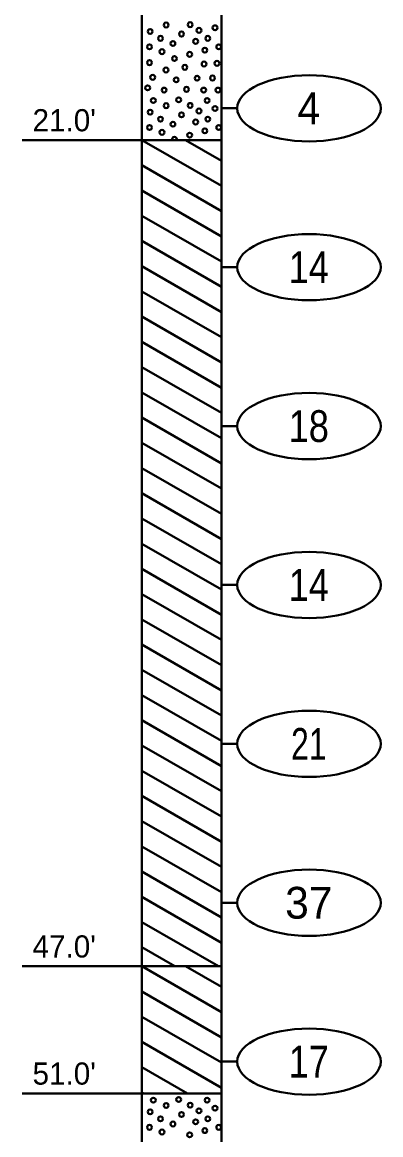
# Model space of a CAD drawing. Extents: x -76 to 974, y -1080 to -735.
# Drawn here: x 11.33 to 22.61, y -820.52 to -785.51 of the extents above; entities that cross this region are included whole.
import ezdxf
from ezdxf.enums import TextEntityAlignment as Align

# ---------------------------------------------------------------- set-up
doc = ezdxf.new("R2010")
doc.units = 0
doc.header["$LTSCALE"] = 0.36
doc.layers.add('27', color=7, linetype='Continuous', lineweight=40)

msp = doc.modelspace()

# ---------------------------------------------------------------- linework, layer by layer
at = {"layer": '27'}
for p, q in [((15.0967, -785.2173), (15.0967, -789.2173)), ((17.5967, -789.2173), (17.5967, -785.2173)), ((18.0967, -788.2173), (17.5967, -788.2173)), ((11.3293, -789.2173), (15.0966, -789.2173)), ((15.0967, -789.2173), (17.5967, -789.2173)), ((15.0967, -789.2173), (17.5967, -790.6607)), ((15.0967, -789.2173), (15.0967, -815.2173)), ((16.4714, -789.2173), (17.5967, -789.8669)), ((16.4714, -789.2173), (17.5967, -789.8669)), ((17.5967, -815.2173), (17.5967, -789.2173)), ((15.0967, -790.011), (17.5967, -791.4544)), ((15.0967, -790.011), (17.5967, -791.4544)), ((15.0967, -790.8048), (17.5967, -792.2482)), ((15.0967, -791.5985), (17.5967, -793.0419)), ((15.0967, -791.5985), (17.5967, -793.0419)), ((15.0967, -792.3923), (17.5967, -793.8357)), ((15.0967, -793.186), (17.5967, -794.6294)), ((15.0967, -793.186), (17.5967, -794.6294)), ((18.0967, -793.2173), (17.5967, -793.2173)), ((15.0967, -793.9798), (17.5967, -795.4232)), ((15.0967, -794.7735), (17.5967, -796.2169)), ((15.0967, -794.7735), (17.5967, -796.2169)), ((15.0967, -795.5673), (17.5967, -797.0107)), ((15.0967, -796.361), (17.5967, -797.8044)), ((15.0967, -796.361), (17.5967, -797.8044)), ((15.0967, -797.1548), (17.5967, -798.5982)), ((15.0967, -797.9485), (17.5967, -799.3919)), ((15.0967, -797.9485), (17.5967, -799.3919)), ((18.0967, -798.2173), (17.5967, -798.2173)), ((15.0967, -798.7423), (17.5967, -800.1857)), ((15.0967, -799.536), (17.5967, -800.9794)), ((15.0967, -799.536), (17.5967, -800.9794)), ((15.0967, -800.3298), (17.5967, -801.7732)), ((15.0967, -801.1235), (17.5967, -802.5669)), ((15.0967, -801.1235), (17.5967, -802.5669)), ((15.0967, -801.9173), (17.5967, -803.3607)), ((15.0967, -802.711), (17.5967, -804.1544)), ((15.0967, -802.711), (17.5967, -804.1544)), ((18.0967, -803.2173), (17.5967, -803.2173)), ((15.0967, -803.5048), (17.5967, -804.9482)), ((15.0967, -804.2985), (17.5967, -805.7419)), ((15.0967, -804.2985), (17.5967, -805.7419)), ((15.0967, -805.0923), (17.5967, -806.5357)), ((15.0967, -805.886), (17.5967, -807.3294)), ((15.0967, -805.886), (17.5967, -807.3294)), ((15.0967, -806.6798), (17.5967, -808.1232)), ((15.0967, -807.4735), (17.5967, -808.9169)), ((15.0967, -807.4735), (17.5967, -808.9169)), ((15.0967, -808.2673), (17.5967, -809.7107)), ((18.0967, -808.2173), (17.5967, -808.2173)), ((15.0967, -809.061), (17.5967, -810.5044)), ((15.0967, -809.061), (17.5967, -810.5044)), ((15.0967, -809.8548), (17.5967, -811.2982)), ((15.0967, -810.6485), (17.5967, -812.0919)), ((15.0967, -810.6485), (17.5967, -812.0919)), ((15.0967, -811.4423), (17.5967, -812.8857)), ((15.0967, -812.236), (17.5967, -813.6794)), ((15.0967, -812.236), (17.5967, -813.6794)), ((15.0967, -813.0298), (17.5967, -814.4732)), ((18.0967, -813.2173), (17.5967, -813.2173)), ((15.0967, -813.8235), (17.5106, -815.2173)), ((15.0967, -813.8235), (17.5106, -815.2173)), ((15.0967, -814.6173), (16.1359, -815.2173)), ((11.3293, -815.2173), (15.0966, -815.2173)), ((15.0967, -815.2173), (17.5967, -815.2173)), ((15.0967, -815.2173), (17.5967, -816.6607)), ((15.0967, -815.2173), (15.0967, -819.2173)), ((16.4714, -815.2173), (17.5967, -815.8669)), ((16.4714, -815.2173), (17.5967, -815.8669)), ((17.5967, -819.2173), (17.5967, -815.2173)), ((15.0967, -816.011), (17.5967, -817.4544)), ((15.0967, -816.011), (17.5967, -817.4544)), ((15.0967, -816.8048), (17.5967, -818.2482)), ((15.0967, -817.5985), (17.5967, -819.0419)), ((15.0967, -817.5985), (17.5967, -819.0419)), ((15.0967, -818.3923), (16.5256, -819.2173)), ((18.0967, -818.2173), (17.5967, -818.2173)), ((15.0967, -819.186), (15.1508, -819.2173)), ((15.0967, -819.186), (15.1508, -819.2173)), ((11.3293, -819.2173), (15.0966, -819.2173)), ((15.0967, -819.2173), (17.5967, -819.2173)), ((15.0967, -819.2173), (15.0967, -838.7173)), ((17.5967, -838.7173), (17.5967, -819.2173))]:
    msp.add_line(p, q, dxfattribs=at)
for points in [[(15.9335, -785.5952), (15.9233, -785.5571), (15.8954, -785.5292), (15.8573, -785.519), (15.8192, -785.5292), (15.7913, -785.5571), (15.7811, -785.5952), (15.7913, -785.6333), (15.8192, -785.6612), (15.8573, -785.6714), (15.8954, -785.6612), (15.9233, -785.6333)], [(16.6886, -785.5862), (16.6784, -785.5481), (16.6505, -785.5202), (16.6124, -785.51), (16.5743, -785.5202), (16.5464, -785.5481), (16.5362, -785.5862), (16.5464, -785.6243), (16.5743, -785.6522), (16.6124, -785.6624), (16.6505, -785.6522), (16.6784, -785.6243)], [(15.4324, -785.7978), (15.4222, -785.7597), (15.3943, -785.7318), (15.3562, -785.7216), (15.3181, -785.7318), (15.2902, -785.7597), (15.28, -785.7978), (15.2902, -785.8359), (15.3181, -785.8638), (15.3562, -785.874), (15.3943, -785.8638), (15.4222, -785.8359)], [(15.7553, -786.0164), (15.7451, -785.9783), (15.7172, -785.9504), (15.6791, -785.9402), (15.641, -785.9504), (15.6131, -785.9783), (15.6029, -786.0164), (15.6131, -786.0545), (15.641, -786.0824), (15.6791, -786.0926), (15.7172, -786.0824), (15.7451, -786.0545)], [(16.4185, -785.881), (16.4083, -785.8429), (16.3804, -785.815), (16.3423, -785.8048), (16.3042, -785.815), (16.2763, -785.8429), (16.2661, -785.881), (16.2763, -785.9191), (16.3042, -785.947), (16.3423, -785.9572), (16.3804, -785.947), (16.4083, -785.9191)], [(16.9668, -785.7634), (16.9566, -785.7253), (16.9287, -785.6974), (16.8906, -785.6872), (16.8525, -785.6974), (16.8246, -785.7253), (16.8144, -785.7634), (16.8246, -785.8015), (16.8525, -785.8294), (16.8906, -785.8396), (16.9287, -785.8294), (16.9566, -785.8015)], [(17.244, -786.0164), (17.2338, -785.9783), (17.2059, -785.9504), (17.1678, -785.9402), (17.1297, -785.9504), (17.1018, -785.9783), (17.0916, -786.0164), (17.1018, -786.0545), (17.1297, -786.0824), (17.1678, -786.0926), (17.2059, -786.0824), (17.2338, -786.0545)], [(17.4741, -785.6821), (17.4639, -785.644), (17.436, -785.6161), (17.3979, -785.6059), (17.3598, -785.6161), (17.3319, -785.644), (17.3217, -785.6821), (17.3319, -785.7202), (17.3598, -785.7481), (17.3979, -785.7583), (17.436, -785.7481), (17.4639, -785.7202)], [(15.4095, -786.2821), (15.3993, -786.244), (15.3714, -786.2161), (15.3333, -786.2059), (15.2952, -786.2161), (15.2673, -786.244), (15.2571, -786.2821), (15.2673, -786.3202), (15.2952, -786.3481), (15.3333, -786.3583), (15.3714, -786.3481), (15.3993, -786.3202)], [(16.1469, -786.1779), (16.1367, -786.1398), (16.1088, -786.1119), (16.0707, -786.1017), (16.0326, -786.1119), (16.0047, -786.1398), (15.9945, -786.1779), (16.0047, -786.216), (16.0326, -786.2439), (16.0707, -786.2541), (16.1088, -786.2439), (16.1367, -786.216)], [(16.8626, -786.1092), (16.8524, -786.0711), (16.8245, -786.0432), (16.7864, -786.033), (16.7483, -786.0432), (16.7204, -786.0711), (16.7102, -786.1092), (16.7204, -786.1473), (16.7483, -786.1752), (16.7864, -786.1854), (16.8245, -786.1752), (16.8524, -786.1473)], [(17.5898, -786.2821), (17.5795, -786.244), (17.5517, -786.2161), (17.5136, -786.2059), (17.4755, -786.2161), (17.4476, -786.244), (17.4374, -786.2821), (17.4476, -786.3202), (17.4755, -786.3481), (17.5136, -786.3583), (17.5517, -786.3481), (17.5795, -786.3202)], [(15.8011, -786.4321), (15.7909, -786.394), (15.763, -786.3661), (15.7249, -786.3559), (15.6868, -786.3661), (15.6589, -786.394), (15.6487, -786.4321), (15.6589, -786.4702), (15.6868, -786.4981), (15.7249, -786.5083), (15.763, -786.4981), (15.7909, -786.4702)], [(16.1952, -786.6508), (16.185, -786.6127), (16.1571, -786.5848), (16.119, -786.5746), (16.0809, -786.5848), (16.053, -786.6127), (16.0428, -786.6508), (16.053, -786.6889), (16.0809, -786.7168), (16.119, -786.727), (16.1571, -786.7168), (16.185, -786.6889)], [(16.6732, -786.5198), (16.663, -786.4817), (16.6351, -786.4539), (16.597, -786.4436), (16.5589, -786.4539), (16.531, -786.4817), (16.5208, -786.5198), (16.531, -786.5579), (16.5589, -786.5858), (16.597, -786.596), (16.6351, -786.5858), (16.663, -786.5579)], [(17.1512, -786.3864), (17.141, -786.3483), (17.1131, -786.3204), (17.075, -786.3102), (17.0369, -786.3204), (17.009, -786.3483), (16.9988, -786.3864), (17.009, -786.4245), (17.0369, -786.4524), (17.075, -786.4626), (17.1131, -786.4524), (17.141, -786.4245)], [(15.4095, -786.7779), (15.3993, -786.7398), (15.3714, -786.7119), (15.3333, -786.7017), (15.2952, -786.7119), (15.2673, -786.7398), (15.2571, -786.7779), (15.2673, -786.816), (15.2952, -786.8439), (15.3333, -786.8541), (15.3714, -786.8439), (15.3993, -786.816)], [(15.9282, -787.0093), (15.918, -786.9712), (15.8901, -786.9433), (15.852, -786.9331), (15.8139, -786.9433), (15.786, -786.9712), (15.7758, -787.0093), (15.786, -787.0474), (15.8139, -787.0753), (15.852, -787.0855), (15.8901, -787.0753), (15.918, -787.0474)], [(16.5232, -786.9254), (16.5129, -786.8873), (16.4851, -786.8594), (16.447, -786.8492), (16.4089, -786.8594), (16.381, -786.8873), (16.3708, -786.9254), (16.381, -786.9635), (16.4089, -786.9914), (16.447, -787.0016), (16.4851, -786.9914), (16.5129, -786.9635)], [(17.1283, -786.8249), (17.1181, -786.7868), (17.0902, -786.759), (17.0521, -786.7487), (17.014, -786.759), (16.9861, -786.7868), (16.9759, -786.8249), (16.9861, -786.863), (17.014, -786.8909), (17.0521, -786.9011), (17.0902, -786.8909), (17.1181, -786.863)], [(17.5325, -786.8008), (17.5223, -786.7627), (17.4944, -786.7348), (17.4563, -786.7246), (17.4182, -786.7348), (17.3904, -786.7627), (17.3801, -786.8008), (17.3904, -786.8389), (17.4182, -786.8668), (17.4563, -786.877), (17.4944, -786.8668), (17.5223, -786.8389)], [(15.5125, -787.2407), (15.5023, -787.2026), (15.4744, -787.1747), (15.4363, -787.1645), (15.3982, -787.1747), (15.3703, -787.2026), (15.3601, -787.2407), (15.3703, -787.2788), (15.3982, -787.3066), (15.4363, -787.3169), (15.4744, -787.3066), (15.5023, -787.2788)], [(16.2511, -787.3207), (16.2409, -787.2826), (16.213, -787.2548), (16.1749, -787.2445), (16.1368, -787.2548), (16.1089, -787.2826), (16.0987, -787.3207), (16.1089, -787.3588), (16.1368, -787.3867), (16.1749, -787.3969), (16.213, -787.3867), (16.2409, -787.3588)], [(16.9084, -787.2699), (16.8981, -787.2318), (16.8703, -787.2039), (16.8322, -787.1937), (16.7941, -787.2039), (16.7662, -787.2318), (16.756, -787.2699), (16.7662, -787.308), (16.7941, -787.3359), (16.8322, -787.3461), (16.8703, -787.3359), (16.8981, -787.308)], [(17.394, -787.2623), (17.3838, -787.2242), (17.3559, -787.1963), (17.3178, -787.1861), (17.2797, -787.1963), (17.2518, -787.2242), (17.2416, -787.2623), (17.2518, -787.3004), (17.2797, -787.3283), (17.3178, -787.3385), (17.3559, -787.3283), (17.3838, -787.3004)], [(15.351, -787.5737), (15.3408, -787.5356), (15.3129, -787.5077), (15.2748, -787.4975), (15.2367, -787.5077), (15.2089, -787.5356), (15.1986, -787.5737), (15.2089, -787.6118), (15.2367, -787.6397), (15.2748, -787.6499), (15.3129, -787.6397), (15.3408, -787.6118)], [(15.8697, -787.6436), (15.8595, -787.6055), (15.8316, -787.5777), (15.7935, -787.5674), (15.7554, -787.5777), (15.7275, -787.6055), (15.7173, -787.6436), (15.7275, -787.6817), (15.7554, -787.7096), (15.7935, -787.7198), (15.8316, -787.7096), (15.8595, -787.6817)], [(16.574, -787.6208), (16.5638, -787.5827), (16.5359, -787.5548), (16.4978, -787.5446), (16.4597, -787.5548), (16.4318, -787.5827), (16.4216, -787.6208), (16.4318, -787.6589), (16.4597, -787.6868), (16.4978, -787.697), (16.5359, -787.6868), (16.5638, -787.6589)], [(17.1168, -787.6436), (17.1066, -787.6055), (17.0787, -787.5777), (17.0406, -787.5674), (17.0025, -787.5777), (16.9746, -787.6055), (16.9644, -787.6436), (16.9746, -787.6817), (17.0025, -787.7096), (17.0406, -787.7198), (17.0787, -787.7096), (17.1066, -787.6817)], [(17.5669, -787.6436), (17.5567, -787.6055), (17.5288, -787.5777), (17.4907, -787.5674), (17.4526, -787.5777), (17.4247, -787.6055), (17.4145, -787.6436), (17.4247, -787.6817), (17.4526, -787.7096), (17.4907, -787.7198), (17.5288, -787.7096), (17.5567, -787.6817)], [(15.5286, -787.9699), (15.5184, -787.9318), (15.4905, -787.9039), (15.4524, -787.8937), (15.4143, -787.9039), (15.3864, -787.9318), (15.3762, -787.9699), (15.3864, -788.008), (15.4143, -788.0359), (15.4524, -788.0461), (15.4905, -788.0359), (15.5184, -788.008)], [(16.3296, -787.9503), (16.3193, -787.9122), (16.2915, -787.8843), (16.2534, -787.8741), (16.2153, -787.8843), (16.1874, -787.9122), (16.1772, -787.9503), (16.1874, -787.9884), (16.2153, -788.0163), (16.2534, -788.0265), (16.2915, -788.0163), (16.3193, -787.9884)], [(16.6886, -788.1262), (16.6784, -788.0881), (16.6505, -788.0602), (16.6124, -788.05), (16.5743, -788.0602), (16.5464, -788.0881), (16.5362, -788.1262), (16.5464, -788.1643), (16.5743, -788.1922), (16.6124, -788.2024), (16.6505, -788.1922), (16.6784, -788.1643)], [(17.2232, -787.97), (17.213, -787.9319), (17.1851, -787.904), (17.147, -787.8938), (17.1089, -787.904), (17.081, -787.9319), (17.0708, -787.97), (17.081, -788.0081), (17.1089, -788.036), (17.147, -788.0462), (17.1851, -788.036), (17.213, -788.0081)], [(15.4324, -788.3378), (15.4222, -788.2997), (15.3943, -788.2718), (15.3562, -788.2616), (15.3181, -788.2718), (15.2902, -788.2997), (15.28, -788.3378), (15.2902, -788.3759), (15.3181, -788.4038), (15.3562, -788.414), (15.3943, -788.4038), (15.4222, -788.3759)], [(15.9335, -788.1352), (15.9233, -788.0971), (15.8954, -788.0692), (15.8573, -788.059), (15.8192, -788.0692), (15.7913, -788.0971), (15.7811, -788.1352), (15.7913, -788.1733), (15.8192, -788.2012), (15.8573, -788.2114), (15.8954, -788.2012), (15.9233, -788.1733)], [(16.4185, -788.421), (16.4083, -788.3829), (16.3804, -788.355), (16.3423, -788.3448), (16.3042, -788.355), (16.2763, -788.3829), (16.2661, -788.421), (16.2763, -788.4591), (16.3042, -788.487), (16.3423, -788.4972), (16.3804, -788.487), (16.4083, -788.4591)], [(16.9668, -788.3034), (16.9566, -788.2653), (16.9287, -788.2374), (16.8906, -788.2272), (16.8525, -788.2374), (16.8246, -788.2653), (16.8144, -788.3034), (16.8246, -788.3415), (16.8525, -788.3694), (16.8906, -788.3796), (16.9287, -788.3694), (16.9566, -788.3415)], [(17.4741, -788.2221), (17.4639, -788.184), (17.436, -788.1561), (17.3979, -788.1459), (17.3598, -788.1561), (17.3319, -788.184), (17.3217, -788.2221), (17.3319, -788.2602), (17.3598, -788.2881), (17.3979, -788.2983), (17.436, -788.2881), (17.4639, -788.2602)], [(15.4095, -788.8221), (15.3993, -788.784), (15.3714, -788.7561), (15.3333, -788.7459), (15.2952, -788.7561), (15.2673, -788.784), (15.2571, -788.8221), (15.2673, -788.8602), (15.2952, -788.8881), (15.3333, -788.8983), (15.3714, -788.8881), (15.3993, -788.8602)], [(15.7553, -788.5564), (15.7451, -788.5183), (15.7172, -788.4904), (15.6791, -788.4802), (15.641, -788.4904), (15.6131, -788.5183), (15.6029, -788.5564), (15.6131, -788.5945), (15.641, -788.6224), (15.6791, -788.6326), (15.7172, -788.6224), (15.7451, -788.5945)], [(16.1469, -788.7179), (16.1367, -788.6798), (16.1088, -788.6519), (16.0707, -788.6417), (16.0326, -788.6519), (16.0047, -788.6798), (15.9945, -788.7179), (16.0047, -788.756), (16.0326, -788.7839), (16.0707, -788.7941), (16.1088, -788.7839), (16.1367, -788.756)], [(16.8626, -788.6492), (16.8524, -788.6111), (16.8245, -788.5832), (16.7864, -788.573), (16.7483, -788.5832), (16.7204, -788.6111), (16.7102, -788.6492), (16.7204, -788.6873), (16.7483, -788.7152), (16.7864, -788.7254), (16.8245, -788.7152), (16.8524, -788.6873)], [(17.244, -788.5564), (17.2338, -788.5183), (17.2059, -788.4904), (17.1678, -788.4802), (17.1297, -788.4904), (17.1018, -788.5183), (17.0916, -788.5564), (17.1018, -788.5945), (17.1297, -788.6224), (17.1678, -788.6326), (17.2059, -788.6224), (17.2338, -788.5945)], [(17.5898, -788.8221), (17.5795, -788.784), (17.5517, -788.7561), (17.5136, -788.7459), (17.4755, -788.7561), (17.4476, -788.784), (17.4374, -788.8221), (17.4476, -788.8602), (17.4755, -788.8881), (17.5136, -788.8983), (17.5517, -788.8881), (17.5795, -788.8602)], [(15.8011, -788.9721), (15.7909, -788.934), (15.763, -788.9061), (15.7249, -788.8959), (15.6868, -788.9061), (15.6589, -788.934), (15.6487, -788.9721), (15.6589, -789.0102), (15.6868, -789.0381), (15.7249, -789.0483), (15.763, -789.0381), (15.7909, -789.0102)], [(16.6732, -789.0598), (16.663, -789.0217), (16.6351, -788.9939), (16.597, -788.9836), (16.5589, -788.9939), (16.531, -789.0217), (16.5208, -789.0598), (16.531, -789.0979), (16.5589, -789.1258), (16.597, -789.136), (16.6351, -789.1258), (16.663, -789.0979)], [(17.1512, -788.9264), (17.141, -788.8883), (17.1131, -788.8604), (17.075, -788.8502), (17.0369, -788.8604), (17.009, -788.8883), (16.9988, -788.9264), (17.009, -788.9645), (17.0369, -788.9924), (17.075, -789.0026), (17.1131, -788.9924), (17.141, -788.9645)], [(16.1952, -789.1908), (16.185, -789.1527), (16.1571, -789.1248), (16.119, -789.1146), (16.0809, -789.1248), (16.053, -789.1527), (16.0428, -789.1908), (16.0499, -789.2173), (16.1881, -789.2173)], [(15.5286, -819.4299), (15.5184, -819.3918), (15.4905, -819.3639), (15.4524, -819.3537), (15.4143, -819.3639), (15.3864, -819.3918), (15.3762, -819.4299), (15.3864, -819.468), (15.4143, -819.4959), (15.4524, -819.5061), (15.4905, -819.4959), (15.5184, -819.468)], [(15.9335, -819.5952), (15.9233, -819.5571), (15.8954, -819.5292), (15.8573, -819.519), (15.8192, -819.5292), (15.7913, -819.5571), (15.7811, -819.5952), (15.7913, -819.6333), (15.8192, -819.6612), (15.8573, -819.6714), (15.8954, -819.6612), (15.9233, -819.6333)], [(16.3296, -819.4103), (16.3193, -819.3722), (16.2915, -819.3443), (16.2534, -819.3341), (16.2153, -819.3443), (16.1874, -819.3722), (16.1772, -819.4103), (16.1874, -819.4484), (16.2153, -819.4763), (16.2534, -819.4865), (16.2915, -819.4763), (16.3193, -819.4484)], [(16.6886, -819.5862), (16.6784, -819.5481), (16.6505, -819.5202), (16.6124, -819.51), (16.5743, -819.5202), (16.5464, -819.5481), (16.5362, -819.5862), (16.5464, -819.6243), (16.5743, -819.6522), (16.6124, -819.6624), (16.6505, -819.6522), (16.6784, -819.6243)], [(17.2232, -819.43), (17.213, -819.3919), (17.1851, -819.364), (17.147, -819.3538), (17.1089, -819.364), (17.081, -819.3919), (17.0708, -819.43), (17.081, -819.4681), (17.1089, -819.496), (17.147, -819.5062), (17.1851, -819.496), (17.213, -819.4681)], [(15.4324, -819.7978), (15.4222, -819.7597), (15.3943, -819.7318), (15.3562, -819.7216), (15.3181, -819.7318), (15.2902, -819.7597), (15.28, -819.7978), (15.2902, -819.8359), (15.3181, -819.8638), (15.3562, -819.874), (15.3943, -819.8638), (15.4222, -819.8359)], [(16.4185, -819.881), (16.4083, -819.8429), (16.3804, -819.815), (16.3423, -819.8048), (16.3042, -819.815), (16.2763, -819.8429), (16.2661, -819.881), (16.2763, -819.9191), (16.3042, -819.947), (16.3423, -819.9572), (16.3804, -819.947), (16.4083, -819.9191)], [(16.9668, -819.7634), (16.9566, -819.7253), (16.9287, -819.6974), (16.8906, -819.6872), (16.8525, -819.6974), (16.8246, -819.7253), (16.8144, -819.7634), (16.8246, -819.8015), (16.8525, -819.8294), (16.8906, -819.8396), (16.9287, -819.8294), (16.9566, -819.8015)], [(17.4741, -819.6821), (17.4639, -819.644), (17.436, -819.6161), (17.3979, -819.6059), (17.3598, -819.6161), (17.3319, -819.644), (17.3217, -819.6821), (17.3319, -819.7202), (17.3598, -819.7481), (17.3979, -819.7583), (17.436, -819.7481), (17.4639, -819.7202)], [(15.4095, -820.2821), (15.3993, -820.244), (15.3714, -820.2161), (15.3333, -820.2059), (15.2952, -820.2161), (15.2673, -820.244), (15.2571, -820.2821), (15.2673, -820.3202), (15.2952, -820.3481), (15.3333, -820.3583), (15.3714, -820.3481), (15.3993, -820.3202)], [(15.7553, -820.0164), (15.7451, -819.9783), (15.7172, -819.9504), (15.6791, -819.9402), (15.641, -819.9504), (15.6131, -819.9783), (15.6029, -820.0164), (15.6131, -820.0545), (15.641, -820.0824), (15.6791, -820.0926), (15.7172, -820.0824), (15.7451, -820.0545)], [(16.1469, -820.1779), (16.1367, -820.1398), (16.1088, -820.1119), (16.0707, -820.1017), (16.0326, -820.1119), (16.0047, -820.1398), (15.9945, -820.1779), (16.0047, -820.216), (16.0326, -820.2439), (16.0707, -820.2541), (16.1088, -820.2439), (16.1367, -820.216)], [(16.8626, -820.1092), (16.8524, -820.0711), (16.8245, -820.0432), (16.7864, -820.033), (16.7483, -820.0432), (16.7204, -820.0711), (16.7102, -820.1092), (16.7204, -820.1473), (16.7483, -820.1752), (16.7864, -820.1854), (16.8245, -820.1752), (16.8524, -820.1473)], [(17.244, -820.0164), (17.2338, -819.9783), (17.2059, -819.9504), (17.1678, -819.9402), (17.1297, -819.9504), (17.1018, -819.9783), (17.0916, -820.0164), (17.1018, -820.0545), (17.1297, -820.0824), (17.1678, -820.0926), (17.2059, -820.0824), (17.2338, -820.0545)], [(17.5898, -820.2821), (17.5795, -820.244), (17.5517, -820.2161), (17.5136, -820.2059), (17.4755, -820.2161), (17.4476, -820.244), (17.4374, -820.2821), (17.4476, -820.3202), (17.4755, -820.3481), (17.5136, -820.3583), (17.5517, -820.3481), (17.5795, -820.3202)], [(15.8011, -820.4321), (15.7909, -820.394), (15.763, -820.3661), (15.7249, -820.3559), (15.6868, -820.3661), (15.6589, -820.394), (15.6487, -820.4321), (15.6589, -820.4702), (15.6868, -820.4981), (15.7249, -820.5083), (15.763, -820.4981), (15.7909, -820.4702)], [(16.6732, -820.5198), (16.663, -820.4817), (16.6351, -820.4539), (16.597, -820.4436), (16.5589, -820.4539), (16.531, -820.4817), (16.5208, -820.5198), (16.531, -820.5579), (16.5589, -820.5858), (16.597, -820.596), (16.6351, -820.5858), (16.663, -820.5579)], [(17.1512, -820.3864), (17.141, -820.3483), (17.1131, -820.3204), (17.075, -820.3102), (17.0369, -820.3204), (17.009, -820.3483), (16.9988, -820.3864), (17.009, -820.4245), (17.0369, -820.4524), (17.075, -820.4626), (17.1131, -820.4524), (17.141, -820.4245)]]:
    msp.add_lwpolyline(points, close=True, dxfattribs=at)
for centre in [(20.3541, -788.2173), (20.3541, -793.2173), (20.3541, -798.2173), (20.3541, -803.2173), (20.3541, -808.2173), (20.3541, -813.2173), (20.3541, -818.2173)]:
    msp.add_ellipse(centre, major_axis=(2.2574, 0), ratio=0.461538, dxfattribs=at)

# ---------------------------------------------------------------- texts
for s, width, p in [('4', 0.95, (20.3469, -788.7172)), ('14', 0.85, (20.3469, -793.7172)), ('18', 0.85, (20.3469, -798.7172)), ('14', 0.85, (20.3469, -803.7172)), ('21', 0.75, (20.3469, -808.7172)), ('17', 0.85, (20.3469, -818.7172))]:
    msp.add_text(s, height=1, dxfattribs=dict(at, width=width)).set_placement(p, align=Align.CENTER)
for s, p in [("21.0'", (11.6533, -788.9409)), ("47.0'", (11.6533, -814.9409)), ("51.0'", (11.6533, -818.9409))]:
    msp.add_text(s, height=0.6976, dxfattribs=at).set_placement(p)
msp.add_text('37', height=1, dxfattribs=at).set_placement((20.3469, -813.7172), align=Align.CENTER)

doc.saveas('drawing.dxf')
